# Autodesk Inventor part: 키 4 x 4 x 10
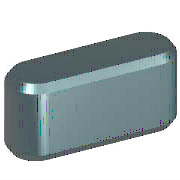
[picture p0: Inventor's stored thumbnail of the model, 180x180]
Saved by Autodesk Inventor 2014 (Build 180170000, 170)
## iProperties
IsCustomPart: 1
Created: 2012-02
Part Number: 키 4 x 4 x 10
Material: 강철, 연강
Description: 키 및 해당 키홈
Document SubType Name: Modeling
Standard: KS B 1311
Designer: mduedu
Standards Organization: KS
Language: ko-KR
Size Designation: 4 x 4 x 10
Categories: <MemberInstance><Categories><Category DisplayName="샤프트 부품" InternalName="7f7aeb1f-a693-4053-b835-cee3144e0d98" Mnemonic="SHFT"><Category DisplayName="키" Interna
Density: 1 g/cm^3
Appearance: 노란색
Author: mduedu
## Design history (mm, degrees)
workplane "Work Plane1"
workplane "Work Plane2"
sketch "스케치1"
  geometry: L1 (2, 2)-(8, 2); L2 (8, -2)-(2, -2); L3 (0, 9.4)-(0, -7.4) reference; L4 (-5, 0)-(30, 0) reference; L5 (10, 0)-(10, 7); A1 r 2 centre (2, 0) between (2, 2) and (2, -2); A2 r 2 centre (8, 0) between (8, -2) and (8, 2)
  constraints: 6 end point, 5 point on circle, 4 tangent, 3 point on line, 2 centre point, 1 horizontal, 1 parallel, 1 perpendicular
  dimensions: "d0" = 2 radius of A1 (= 0.5 x PB); "d13" = 2 radius of A2 (= 0.5 x PB); "d14" = 10 distance between parallel lines of L5 L3 (= NLG)
extrude "본체1" new body sketch "스케치1" taper "d3" = 0 deg; stored distance "d4" = 10
workplane "Work Plane3"
body "Solid1"
chamfer "모따기1" distance "d8" = 0.25 (= PHH); stored, may be unused: second distance "d9" = 0.25 (= PHH), angle "d15" = 45 deg
other parameters: "d1" = -2.5 (= -PNT), "d2" = 1.5 (= PH - PNT), "NLG" = 10 [user parameter; used in 3 equation terms], "PB" = 4 [user parameter; used in 2 equation terms], "PNT" = 2.5 [user parameter; used in 2 equation terms], "PH" = 4 [user parameter; used in 1 equation term], "PHH" = 0.25 [user parameter; used in 2 equation terms], "d10" = 0, "d16" = 0, "d17" = 0, "d18" = 0, "WDMAX" = 12 [user parameter], "RR" = 0.08 [user parameter], "PUEB" = 1.8 [user parameter]
